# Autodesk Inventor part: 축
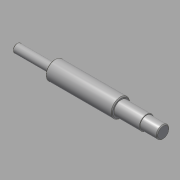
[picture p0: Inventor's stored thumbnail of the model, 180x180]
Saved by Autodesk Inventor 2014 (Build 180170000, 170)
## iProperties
Created: 2016-05
Part Number: 축
Document SubType Name: Modeling
Designer: mduedu
Density: 7.86 g/cm^3
Material: 강철, 연강
Appearance: 강철
Author: mduedu
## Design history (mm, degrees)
sketch "스케치1"
  geometry: L1 (-42, 11)-(-42, 5); L2 (37, 11)-(37, 8.5); L3 (-87, 0)-(87, 0); L4 (-42, 11)-(37, 11); L5 (37, 11)-(37, 8.5); L6 (-42, 11)-(-42, 5); L7 (-42, 5)-(-87, 5); L8 (-87, 5)-(-87, 0); L9 (37, 8.5)-(67, 8.5); L10 (87, 7.5)-(87, 0); L11 (67, 8.5)-(67, 7.5); L12 (67, 7.5)-(87, 7.5); 1 further point
  constraints: 24 end point, 9 perpendicular, 2 midpoint, 1 horizontal
  dimensions: "d0" = 22 diameter of L4 L3; "d1" = 10 diameter of L7 L3; "d2" = 45 distance between parallel lines of L8 L1; "d3" = 50 distance between parallel lines of L10 L2; "d4" = 15 diameter of L12 L3; "d5" = 20 distance between parallel lines of L10 L11; "d29" = 79 distance of L1.start L2.start; "d37" = 17 diameter of L9 L3
revolve "회전1" stored, may be unused: angle "d6" = 90 deg
chamfer "모따기2" distance "d32" = 1; stored, may be unused: second distance "d33" = 2, angle "d34" = 45 deg
node "작업 평면4"
sketch "스케치4"
  geometry: L1 (-5, 2.5)-(5, 2.5); L2 (5, -2.5)-(-5, -2.5); L3 (-10, -6.5)-(-10, 6.5) reference; A1 r 2.5 centre (5, 0) between (5, -2.5) and (5, 2.5); A2 r 2.5 centre (-5, 0) between (-5, 2.5) and (-5, -2.5); 1 further point
  constraints: 4 end point, 4 point on circle, 4 tangent, 2 centre point, 1 horizontal, 1 horizontal alignment, 1 parallel
  dimensions: "d20" = 5 distance between parallel lines of L2 L1; "d21" = 15 dimension on A1 A2; "d35" = 2.5 distance edge to line of A2 L3
extrude "돌출3" cut sketch "스케치4" distance "d23" = 3; taper "d24" = 0 deg
node "작업 평면5"
sketch "스케치5"
  geometry: L1 (22.5, 1.5)-(10, 1.5); L2 (10, -1.5)-(22.5, -1.5); L3 (22.5, 4)-(22.5, -4) reference; A1 r 1.5 centre (10, 0) between (10, 1.5) and (10, -1.5); 3 further points
  constraints: 4 end point, 2 horizontal alignment, 2 point on circle, 2 point on line, 2 tangent, 1 centre point, 1 coincident, 1 horizontal, 1 midpoint
  dimensions: "d25" = 3 distance between parallel lines of L2 L1; "d36" = 14 dimension on A1 L3
extrude "돌출4" cut sketch "스케치5" distance "d27" = 1.8; taper "d28" = 0 deg
node "솔리드1"
